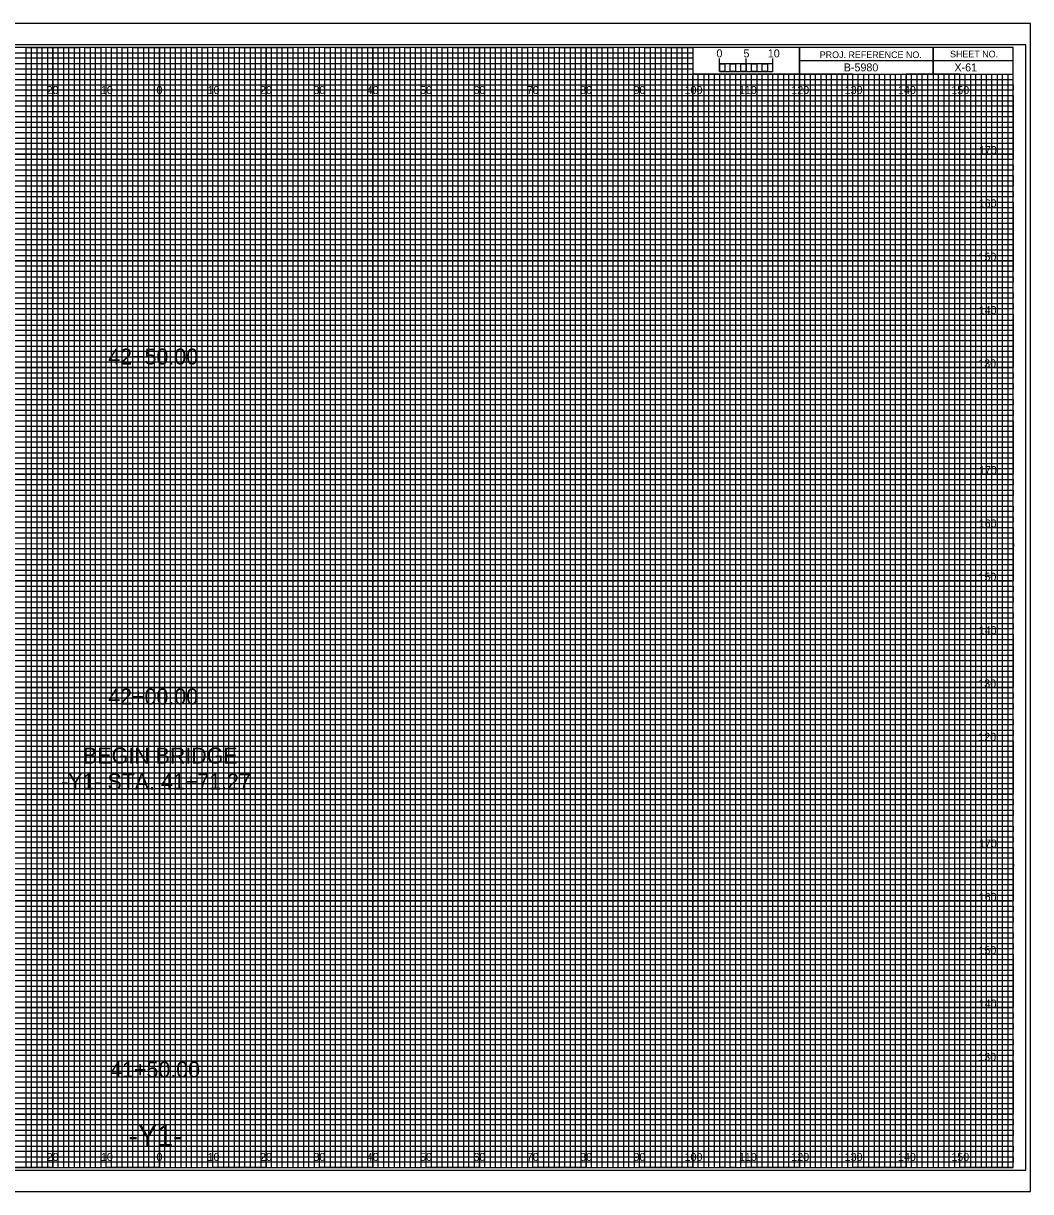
# Model space of a CAD drawing. Extents: x -13 to 323, y -5 to 4834.
# Drawn here: x 134.5 to 323.3, y 3295.5 to 3514.5 of the extents above; entities that cross this region are included whole.
import ezdxf

# ---------------------------------------------------------------- set-up
doc = ezdxf.new("R2010")
doc.units = 0
for name, color, linetype in [('Exist CMT Pavement', 7, 'Continuous'), ('Exist Cross Section Cell', 7, 'Continuous'), ('Exist XS Center Line Elevation Label', 7, 'Continuous'), ('Exist XS Ground Line', 7, 'Continuous'), ('Prop CMT Pvmt Course 1', 7, 'Continuous'), ('Prop CMT Pvmt Course 1 Wedge', 7, 'Continuous'), ('Prop CMT Pvmt Course 2', 7, 'Continuous'), ('Prop CMT Pvmt Course 2 Wedge', 7, 'Continuous'), ('Prop CMT Pvmt Course 3', 7, 'Continuous'), ('Prop CMT Pvmt Course 3 Wedge', 7, 'Continuous'), ('Prop CMT Pvmt Surface', 7, 'Continuous'), ('Prop CMT Pvmt Surface Shoulder', 7, 'Continuous'), ('Prop CMT Shld Paved Course 1', 7, 'Continuous'), ('Prop CMT Shld Paved Course 2', 7, 'Continuous'), ('Prop CMT Shld Paved Course 3', 7, 'Continuous'), ('Prop CMT Slope Grass', 7, 'Continuous'), ('Prop CMT Subgrade Earthwork', 7, 'Continuous')]:
    doc.layers.add(name, color=color, linetype=linetype)

msp = doc.modelspace()

# ---------------------------------------------------------------- linework, layer by layer
at = {"layer": 'Exist XS Center Line Elevation Label'}
for points in [[(125, 3300), (135, 3300), (135, 3510), (145, 3510), (145, 3300), (155, 3300), (155, 3510), (165, 3510), (165, 3300), (175, 3300), (175, 3510), (185, 3510), (185, 3300), (195, 3300), (195, 3510), (205, 3510), (205, 3300), (215, 3300), (215, 3510), (225, 3510), (225, 3300), (235, 3300), (235, 3510), (245, 3510), (245, 3300), (255, 3300), (255, 3510), (259.93, 3510), (260, 3510), (260, 3505), (264.99, 3505), (264.99, 3300), (275, 3300), (275, 3505), (285, 3505), (285, 3300), (295, 3300), (295, 3505), (305, 3505), (305, 3300), (315, 3300), (315, 3505)], [(0, 3505), (275, 3505)], [(0, 3485), (320, 3485), (320, 3495), (0, 3495)], [(0, 3465), (320, 3465), (320, 3475), (0, 3475)], [(0, 3445), (320, 3445), (320, 3455), (0, 3455)], [(0, 3425), (320, 3425), (320, 3435), (0, 3435)], [(0, 3405), (320, 3405), (320, 3415), (0, 3415)], [(0, 3385), (320, 3385), (320, 3395), (0, 3395)], [(0, 3365), (320, 3365), (320, 3375), (0, 3375)], [(0, 3345), (320, 3345), (320, 3355), (0, 3355)], [(0, 3325), (320, 3325), (320, 3335), (0, 3335)], [(0, 3305), (320, 3305), (320, 3315), (0, 3315)]]:
    msp.add_lwpolyline(points, dxfattribs=at)
at = {"layer": 'Exist XS Ground Line'}
for p, q in [((150, 3510), (140, 3510)), ((140, 3510), (140, 3300)), ((150, 3300), (150, 3510)), ((170, 3510), (160, 3510)), ((160, 3510), (160, 3300)), ((170, 3300), (170, 3510)), ((190, 3510), (180, 3510)), ((180, 3510), (180, 3300)), ((190, 3300), (190, 3510)), ((210, 3510), (200, 3510)), ((200, 3510), (200, 3300)), ((210, 3300), (210, 3510)), ((230, 3510), (220, 3510)), ((220, 3510), (220, 3300)), ((230, 3300), (230, 3510)), ((250, 3510), (240, 3510)), ((240, 3510), (240, 3300)), ((250, 3300), (250, 3510)), ((260, 3510), (260, 3300)), ((270, 3300), (270, 3505)), ((290, 3505), (280, 3505)), ((280, 3505), (280, 3300)), ((290, 3300), (290, 3505)), ((310, 3505), (300, 3505)), ((300, 3505), (300, 3300)), ((310, 3300), (310, 3505)), ((140, 3300), (130, 3300)), ((160, 3300), (150, 3300)), ((180, 3300), (170, 3300)), ((200, 3300), (190, 3300)), ((220, 3300), (210, 3300)), ((240, 3300), (230, 3300)), ((260, 3300), (250, 3300)), ((280, 3300), (270, 3300)), ((300, 3300), (290, 3300)), ((320, 3300), (310, 3300)), ((320, 3300), (320, 3300))]:
    msp.add_line(p, q, dxfattribs=at)
for points in [[(0, 3500), (320, 3500), (320, 3490), (0, 3490)], [(0, 3480), (320, 3480), (320, 3470), (0, 3470)], [(0, 3460), (320, 3460), (320, 3450), (0, 3450)], [(0, 3440), (320, 3440), (320, 3430), (0, 3430)], [(0, 3420), (320, 3420), (320, 3410), (0, 3410)], [(0, 3400), (320, 3400), (320, 3390), (0, 3390)], [(0, 3380), (320, 3380), (320, 3370), (0, 3370)], [(0, 3360), (320, 3360), (320, 3350), (0, 3350)], [(0, 3340), (320, 3340), (320, 3330), (0, 3330)], [(0, 3320), (320, 3320), (320, 3310), (0, 3310)]]:
    msp.add_lwpolyline(points, dxfattribs=at)
at = {"layer": 'Prop CMT Pvmt Course 1'}
for p, q in [((267, 3505), (266.01, 3505)), ((266.01, 3505), (266.01, 3300)), ((267, 3300), (267, 3505)), ((269, 3505), (268, 3505)), ((268, 3505), (268, 3300)), ((269, 3300), (269, 3505)), ((266.01, 3300), (265, 3300)), ((268, 3300), (267, 3300))]:
    msp.add_line(p, q, dxfattribs=at)
for points in [[(135, 3300), (136, 3300), (136, 3510), (137, 3510), (137, 3300)], [(137, 3300), (138, 3300), (138, 3510), (139, 3510), (139, 3300)], [(140, 3300), (141, 3300), (141, 3510), (142, 3510), (142, 3300)], [(142, 3300), (143, 3300), (143, 3510), (144, 3510), (144, 3300)], [(145, 3300), (146, 3300), (146, 3510), (147, 3510), (147, 3300)], [(147, 3300), (148, 3300), (148, 3510), (149, 3510), (149, 3300)], [(150, 3300), (151, 3300), (151, 3510), (152, 3510), (152, 3300)], [(152, 3300), (153, 3300), (153, 3510), (154, 3510), (154, 3300)], [(155, 3300), (156, 3300), (156, 3510), (157, 3510), (157, 3300)], [(157, 3300), (158, 3300), (158, 3510), (159, 3510), (159, 3300)], [(160, 3300), (161, 3300), (161, 3510), (162, 3510), (162, 3300)], [(162, 3300), (163, 3300), (163, 3510), (164, 3510), (164, 3300)], [(165, 3300), (166, 3300), (166, 3510), (167, 3510), (167, 3300)], [(167, 3300), (168, 3300), (168, 3510), (169, 3510), (169, 3300)], [(170, 3300), (171, 3300), (171, 3510), (172, 3510), (172, 3300)], [(172, 3300), (173, 3300), (173, 3510), (174, 3510), (174, 3300)], [(175, 3300), (176, 3300), (176, 3510), (177, 3510), (177, 3300)], [(177, 3300), (178, 3300), (178, 3510), (179, 3510), (179, 3300)], [(180, 3300), (181, 3300), (181, 3510), (182, 3510), (182, 3300)], [(182, 3300), (183, 3300), (183, 3510), (184, 3510), (184, 3300)], [(185, 3300), (186, 3300), (186, 3510), (187, 3510), (187, 3300)], [(187, 3300), (188, 3300), (188, 3510), (189, 3510), (189, 3300)], [(190, 3300), (191, 3300), (191, 3510), (192, 3510), (192, 3300)], [(192, 3300), (193, 3300), (193, 3510), (194, 3510), (194, 3300)], [(195, 3300), (196, 3300), (196, 3510), (197, 3510), (197, 3300)], [(197, 3300), (198, 3300), (198, 3510), (199, 3510), (199, 3300)], [(200, 3300), (201, 3300), (201, 3510), (202, 3510), (202, 3300)], [(202, 3300), (203, 3300), (203, 3510), (204, 3510), (204, 3300)], [(205, 3300), (206, 3300), (206, 3510), (207, 3510), (207, 3300)], [(207, 3300), (208, 3300), (208, 3510), (209, 3510), (209, 3300)], [(210, 3300), (211, 3300), (211, 3510), (212, 3510), (212, 3300)], [(212, 3300), (213, 3300), (213, 3510), (214, 3510), (214, 3300)], [(215, 3300), (216, 3300), (216, 3510), (217, 3510), (217, 3300)], [(217, 3300), (218, 3300), (218, 3510), (219, 3510), (219, 3300)], [(220, 3300), (221, 3300), (221, 3510), (222, 3510), (222, 3300)], [(222, 3300), (223, 3300), (223, 3510), (224, 3510), (224, 3300)], [(225, 3300), (226, 3300), (226, 3510), (227, 3510), (227, 3300)], [(227, 3300), (228, 3300), (228, 3510), (229, 3510), (229, 3300)], [(230, 3300), (231, 3300), (231, 3510), (232, 3510), (232, 3300)], [(232, 3300), (233, 3300), (233, 3510), (234, 3510), (234, 3300)], [(235, 3300), (236, 3300), (236, 3510), (237, 3510), (237, 3300)], [(237, 3300), (238, 3300), (238, 3510), (239, 3510), (239, 3300)], [(240, 3300), (241, 3300), (241, 3510), (242, 3510), (242, 3300)], [(242, 3300), (243, 3300), (243, 3510), (244, 3510), (244, 3300)], [(245, 3300), (246, 3300), (246, 3510), (247, 3510), (247, 3300)], [(247, 3300), (248, 3300), (248, 3510), (249, 3510), (249, 3300)], [(250, 3300), (251, 3300), (251, 3510), (252, 3510), (252, 3300)], [(252, 3300), (253, 3300), (253, 3510), (254, 3510), (254, 3300)], [(255, 3300), (256, 3300), (256, 3510), (257, 3510), (257, 3300)], [(257, 3300), (258, 3300), (258, 3510), (259, 3510), (259, 3300)], [(260, 3300), (261, 3300), (261, 3505), (262.02, 3505), (262.02, 3300)], [(262, 3300), (263, 3300), (263, 3505), (263.99, 3505), (263.99, 3300)], [(270, 3300), (270.98, 3300), (270.98, 3505), (272, 3505), (272, 3300)], [(272, 3300), (273, 3300), (273, 3505), (274.05, 3505), (274.05, 3300)], [(275, 3300), (276, 3300), (276, 3505), (277, 3505), (277, 3300)], [(277, 3300), (278, 3300), (278, 3505), (279, 3505), (279, 3300)], [(280, 3300), (281, 3300), (281, 3505), (282, 3505), (282, 3300)], [(282, 3300), (283, 3300), (283, 3505), (284, 3505), (284, 3300)], [(285, 3300), (286, 3300), (286, 3505), (287, 3505), (287, 3300)], [(287, 3300), (288, 3300), (288, 3505), (289, 3505), (289, 3300)], [(290, 3300), (291, 3300), (291, 3505), (292, 3505), (292, 3300)], [(292, 3300), (293, 3300), (293, 3505), (294, 3505), (294, 3300)], [(295, 3300), (296, 3300), (296, 3505), (297, 3505), (297, 3300)], [(297, 3300), (298, 3300), (298, 3505), (299, 3505), (299, 3300)], [(300, 3300), (301, 3300), (301, 3505), (302, 3505), (302, 3300)], [(302, 3300), (303, 3300), (303, 3505), (304, 3505), (304, 3300)], [(305, 3300), (306, 3300), (306, 3505), (307, 3505), (307, 3300)], [(307, 3300), (308, 3300), (308, 3505), (309, 3505), (309, 3300)], [(310, 3300), (311, 3300), (311, 3505), (312, 3505), (312, 3300)], [(312, 3300), (313, 3300), (313, 3505), (314, 3505), (314, 3300)], [(315, 3300), (316, 3300), (316, 3505), (317, 3505), (317, 3300)], [(317, 3300), (318, 3300), (318, 3505), (319, 3505), (319, 3300)]]:
    msp.add_lwpolyline(points, dxfattribs=at)
at = {"layer": 'Prop CMT Pvmt Course 2'}
for p, q in [((323.3, 3514.5), (-13.4, 3514.5)), ((-13.4, 3295.5), (323.3, 3295.5))]:
    msp.add_line(p, q, dxfattribs=at)
at = {"layer": 'Prop CMT Pvmt Surface Shoulder'}
for p, q in [((305, 3510), (305, 3505)), ((305, 3505), (305, 3510)), ((280, 3507.5), (280, 3505)), ((320, 3507.49), (280, 3507.49)), ((280, 3505), (320, 3505))]:
    msp.add_line(p, q, dxfattribs=at)
for points in [[(320, 3510), (0, 3510), (0, 3300), (320, 3300)], [(280, 3510), (260, 3510), (260, 3505.03), (280, 3505.03)], [(320, 3510), (280, 3510), (280, 3505), (320, 3505)]]:
    msp.add_lwpolyline(points, close=True, dxfattribs=at)
at = {"layer": 'Prop CMT Shld Paved Course 1'}
msp.add_lwpolyline([(-13.4, 3295.5), (323.3, 3295.5), (323.3, 3514.5), (-13.4, 3514.5)], close=True, dxfattribs=at)
at = {"layer": 'Prop CMT Shld Paved Course 2'}
msp.add_lwpolyline([(-10.8, 3299.5), (322.4, 3299.5), (322.4, 3510.5), (-10.8, 3510.5)], close=True, dxfattribs=at)
at = {"layer": 'Prop CMT Shld Paved Course 3'}
for p, q in [((140, 3300), (140, 3510)), ((150, 3300), (150, 3510)), ((160, 3300), (160, 3510)), ((170, 3300), (170, 3510)), ((180, 3300), (180, 3510)), ((190, 3300), (190, 3510)), ((200, 3300), (200, 3510)), ((210, 3300), (210, 3510)), ((220, 3300), (220, 3510)), ((230, 3300), (230, 3510)), ((240, 3300), (240, 3510)), ((250, 3300), (250, 3510)), ((260, 3300), (260, 3504.69)), ((270, 3300), (270, 3504.69)), ((280, 3300), (280, 3504.69)), ((290, 3300), (290, 3504.69)), ((300, 3300), (300, 3504.69)), ((310, 3300), (310, 3504.69)), ((0, 3500), (320, 3500)), ((0, 3490), (320, 3490)), ((0, 3480), (320, 3480)), ((0, 3470), (320, 3470)), ((0, 3460), (320, 3460)), ((0, 3450), (320, 3450)), ((0, 3440), (320, 3440)), ((0, 3430), (320, 3430)), ((0, 3420), (320, 3420)), ((0, 3410), (320, 3410)), ((0, 3400), (320, 3400)), ((0, 3390), (320, 3390)), ((0, 3380), (320, 3380)), ((0, 3370), (320, 3370)), ((0, 3360), (320, 3360)), ((0, 3350), (320, 3350)), ((0, 3340), (320, 3340)), ((0, 3330), (320, 3330)), ((0, 3320), (320, 3320)), ((0, 3310), (320, 3310))]:
    msp.add_line(p, q, dxfattribs=at)
at = {"layer": 'Prop CMT Slope Grass'}
for p, q in [((0, 3509), (260, 3509)), ((260, 3509), (260, 3507.98)), ((260, 3507.98), (0, 3507.98)), ((0, 3507), (260, 3507)), ((260, 3507), (260, 3505.89)), ((260, 3505.89), (0, 3505.89)), ((0, 3504), (320, 3504))]:
    msp.add_line(p, q, dxfattribs=at)
for points in [[(0, 3503), (270, 3503), (320, 3503), (320, 3502), (0, 3502)], [(0, 3501), (320, 3501), (320, 3499), (0, 3499)], [(0, 3498), (320, 3498), (320, 3497), (0, 3496.98)], [(0, 3496), (320, 3496), (320, 3494), (0, 3494)], [(0, 3493), (320, 3493), (320, 3492), (0, 3492)], [(0, 3491), (320, 3491), (320, 3489), (0, 3489)], [(0, 3488), (320, 3488), (320, 3487), (0, 3487)], [(0, 3486), (320, 3486), (320, 3484), (0, 3484)], [(0, 3483), (320, 3483), (320, 3482), (0, 3482)], [(0, 3481), (320, 3481), (320, 3479), (0, 3479)], [(0, 3478), (320, 3478), (320, 3477), (0, 3477)], [(0, 3476), (320, 3476), (320, 3473.95), (320, 3473), (320, 3472), (0, 3472)], [(0, 3474), (320, 3474), (320, 3473), (0, 3473)], [(0, 3471), (320, 3471), (320, 3469), (0, 3469.03)], [(0, 3469.03), (320, 3469), (320, 3468), (0, 3468)], [(0, 3467), (320, 3467), (320, 3466), (0, 3466)], [(0, 3464), (320, 3464), (320, 3463), (0, 3463)], [(0, 3462), (320, 3462), (320, 3461), (0, 3461)], [(-0.07, 3458.89), (320, 3458.89), (320, 3457.88), (-0.07, 3457.88)], [(0, 3457), (320, 3457), (320, 3456), (0, 3456)], [(0, 3454), (320, 3454), (320, 3453), (0, 3453)], [(0, 3452), (320, 3452), (320, 3451), (0, 3451)], [(0, 3449), (320, 3449), (320, 3448), (0, 3448)], [(0, 3447), (320, 3447), (320, 3446), (0, 3446)], [(0, 3444), (320, 3444), (320, 3443), (0, 3443)], [(0, 3442), (320, 3442), (320, 3441), (0, 3441)], [(0, 3439), (320, 3439), (319.99, 3437.98), (0, 3438)], [(0, 3437), (320, 3437), (320, 3436), (0, 3436)], [(0, 3434), (320, 3434), (320, 3433), (0, 3433)], [(0, 3432), (320, 3432), (320, 3431), (0, 3431)], [(0, 3429), (320, 3429), (320, 3428), (0, 3428)], [(0, 3427), (320, 3427), (320, 3426), (0, 3426)], [(0, 3424), (320, 3424), (320, 3423), (0, 3423)], [(0, 3422), (320, 3422), (320, 3421), (0, 3421)], [(0, 3419), (320, 3419), (320, 3418), (0, 3418)], [(0, 3416.99), (320.07, 3416.91), (320, 3416), (0, 3416)], [(0, 3414), (320, 3414), (320, 3413), (0, 3413)], [(0, 3412), (320, 3412), (320, 3411), (0, 3411)], [(0, 3409), (320, 3409), (320, 3408), (0, 3408)], [(0, 3407), (320, 3407), (320, 3406), (0, 3406)], [(0, 3404), (320, 3404), (320, 3403), (0, 3403)], [(0, 3402), (320, 3402), (320, 3401), (0, 3401)], [(0, 3399), (320, 3399), (320, 3398), (0, 3398)], [(0, 3397), (320, 3397), (320, 3396), (0, 3396)], [(0, 3394), (320, 3394), (320, 3393), (0, 3393)], [(0, 3392), (320, 3392), (320, 3391), (0, 3391)], [(0, 3389), (320, 3389), (320, 3388), (0, 3388)], [(0, 3387), (320, 3387), (320, 3386), (0, 3386)], [(0, 3384), (320, 3384), (320, 3383), (0, 3383)], [(0, 3382), (320, 3382), (320, 3381), (0, 3381)], [(0, 3379), (320, 3379), (319.99, 3377.98), (0, 3378)], [(0, 3377), (320, 3377), (320, 3376), (0, 3376)], [(0, 3374), (320, 3374), (320, 3373), (0, 3373)], [(0, 3372), (320, 3372), (320, 3371), (0, 3371)], [(0, 3369), (320, 3369), (320, 3368), (0, 3368)], [(0, 3367), (320, 3367), (320, 3366), (0, 3366)], [(0, 3364), (320, 3364), (320, 3363), (0, 3363)], [(0, 3362), (320, 3362), (320, 3361), (0, 3361)], [(0, 3359), (320, 3359), (320, 3358), (0, 3358)], [(0, 3356.99), (320.07, 3356.91), (320, 3356), (0, 3356)], [(0, 3354), (320, 3354), (320, 3353), (0, 3353)], [(0, 3352), (320, 3352), (320, 3351), (0, 3351)], [(0, 3349), (320, 3349), (320, 3348), (0, 3348)], [(0, 3347), (320, 3347), (320, 3346), (0, 3346)], [(0, 3344), (320, 3344), (320, 3343), (0, 3343)], [(0, 3342), (320, 3342), (320, 3341), (0, 3341)], [(0, 3339), (320, 3339), (320, 3338), (0, 3338)], [(0, 3337), (320, 3337), (320, 3336), (0, 3336)], [(0, 3334), (320, 3334), (320, 3333), (0, 3333)], [(0, 3332), (320, 3332), (320, 3331), (0, 3331)], [(0, 3329), (320, 3329), (320, 3328), (0, 3328)], [(0, 3327), (320, 3327), (320, 3326), (0, 3326)], [(0, 3324), (320, 3324), (320, 3323), (0, 3323)], [(0, 3322), (320, 3322), (320, 3321), (0, 3321)], [(0, 3319), (320, 3319), (320, 3318), (0, 3318)], [(0, 3317), (320, 3317), (320, 3316), (0, 3316)], [(0, 3314), (320, 3314), (320, 3313), (0, 3313)], [(0, 3312), (320, 3312), (320, 3311), (0, 3311)], [(0, 3309), (320, 3309), (320, 3308), (0, 3308)], [(0, 3307), (320, 3307), (320, 3306), (0, 3306)], [(0, 3304), (320, 3304), (320, 3303), (0, 3303)], [(0, 3302), (320, 3302), (320, 3301), (0, 3301)]]:
    msp.add_lwpolyline(points, dxfattribs=at)
at = {"layer": 'Prop CMT Subgrade Earthwork'}
for p, q in [((265, 3505.49), (265, 3507.9)), ((265, 3506.9), (265, 3507.9)), ((270, 3505.49), (270, 3507.9)), ((275, 3505.49), (275, 3507.9)), ((275, 3506.9), (275, 3507.9))]:
    msp.add_line(p, q, dxfattribs=at)
for points in [[(275, 3506.9), (265, 3506.9), (265, 3505.49), (275, 3505.49)], [(265, 3506.9), (266, 3506.9), (266, 3505.49), (265, 3505.49)], [(267, 3506.9), (268, 3506.9), (268, 3505.49), (267, 3505.49)], [(269, 3506.9), (270, 3506.9), (270, 3505.49), (269, 3505.49)], [(271, 3506.9), (272, 3506.9), (272, 3505.49), (271, 3505.49)], [(273, 3506.9), (274, 3506.9), (274, 3505.49), (273, 3505.49)]]:
    msp.add_lwpolyline(points, close=True, dxfattribs=at)

# ---------------------------------------------------------------- texts
at = {"layer": 'Exist CMT Pavement'}
msp.add_text('-Y1-', height=4, dxfattribs=at).set_placement((154.21, 3304))
at = {"layer": 'Exist Cross Section Cell'}
for s, p in [('20', (138.86, 3501.25)), ('10', (149.04, 3501.25)), ('0', (159.45, 3501.25)), ('0', (159.45, 3501.25)), ('10', (169.04, 3501.25)), ('20', (178.86, 3501.25)), ('30', (188.86, 3501.25)), ('40', (198.86, 3501.25)), ('50', (208.86, 3501.25)), ('60', (218.86, 3501.25)), ('70', (228.86, 3501.25)), ('80', (238.86, 3501.25)), ('90', (248.86, 3501.25)), ('100', (258.44, 3501.25)), ('110', (268.62, 3501.25)), ('120', (278.44, 3501.25)), ('130', (288.44, 3501.25)), ('140', (298.44, 3501.25)), ('150', (308.44, 3501.25)), ('20', (138.86, 3301.25)), ('10', (149.04, 3301.25)), ('0', (159.45, 3301.25)), ('0', (159.45, 3301.25)), ('10', (169.04, 3301.25)), ('20', (178.86, 3301.25)), ('30', (188.86, 3301.25)), ('40', (198.86, 3301.25)), ('50', (208.86, 3301.25)), ('60', (218.86, 3301.25)), ('70', (228.86, 3301.25)), ('80', (238.86, 3301.25)), ('90', (248.86, 3301.25)), ('100', (258.44, 3301.25)), ('110', (268.62, 3301.25)), ('120', (278.44, 3301.25)), ('130', (288.44, 3301.25)), ('140', (298.44, 3301.25)), ('150', (308.44, 3301.25))]:
    msp.add_text(s, height=1.5, dxfattribs=at).set_placement(p)
at = {"layer": 'Prop CMT Pvmt Course 1 Wedge'}
for s, p in [('42+50.00', (150.41, 3450.54)), ('42+00.00', (150.41, 3386.81)), ('BEGIN BRIDGE', (145.69, 3375.74)), ('-Y1- STA. 41+71.27', (141.56, 3370.87)), ('41+50.00', (150.77, 3316.89))]:
    msp.add_text(s, height=3, dxfattribs=at).set_placement(p)
at = {"layer": 'Prop CMT Pvmt Course 2 Wedge'}
msp.add_text('X-61', height=1.5, dxfattribs=at).set_placement((309.02, 3505.5))
at = {"layer": 'Prop CMT Pvmt Course 3'}
for s, p in [('170', (313.61, 3490)), ('160', (313.57, 3480)), ('150', (313.52, 3470)), ('140', (313.57, 3460)), ('130', (313.49, 3450)), ('170', (313.61, 3430)), ('160', (313.57, 3420)), ('150', (313.52, 3410)), ('140', (313.57, 3400)), ('130', (313.49, 3390)), ('120', (313.5, 3380)), ('170', (313.61, 3360)), ('160', (313.57, 3350)), ('150', (313.52, 3340)), ('140', (313.57, 3330)), ('130', (313.49, 3320))]:
    msp.add_text(s, height=1.5, dxfattribs=at).set_placement(p)
at = {"layer": 'Prop CMT Pvmt Course 3 Wedge'}
msp.add_text('B-5980', height=1.5, dxfattribs=at).set_placement((288.28, 3505.5))
at = {"layer": 'Prop CMT Pvmt Surface'}
for s, p in [('5', (269.47, 3508.12)), ('10', (274.04, 3508.12))]:
    msp.add_text(s, height=1.5, dxfattribs=at).set_placement(p)
at = {"layer": 'Prop CMT Pvmt Surface Shoulder'}
for s, p in [('PROJ. REFERENCE NO.', (283.77, 3507.99)), ('SHEET NO.', (308.19, 3508.12))]:
    msp.add_text(s, height=1.25, dxfattribs=at).set_placement(p)
at = {"layer": 'Prop CMT Subgrade Earthwork'}
msp.add_text('0', height=1.5, dxfattribs=at).set_placement((264.41, 3508.12))

doc.saveas('drawing.dxf')
